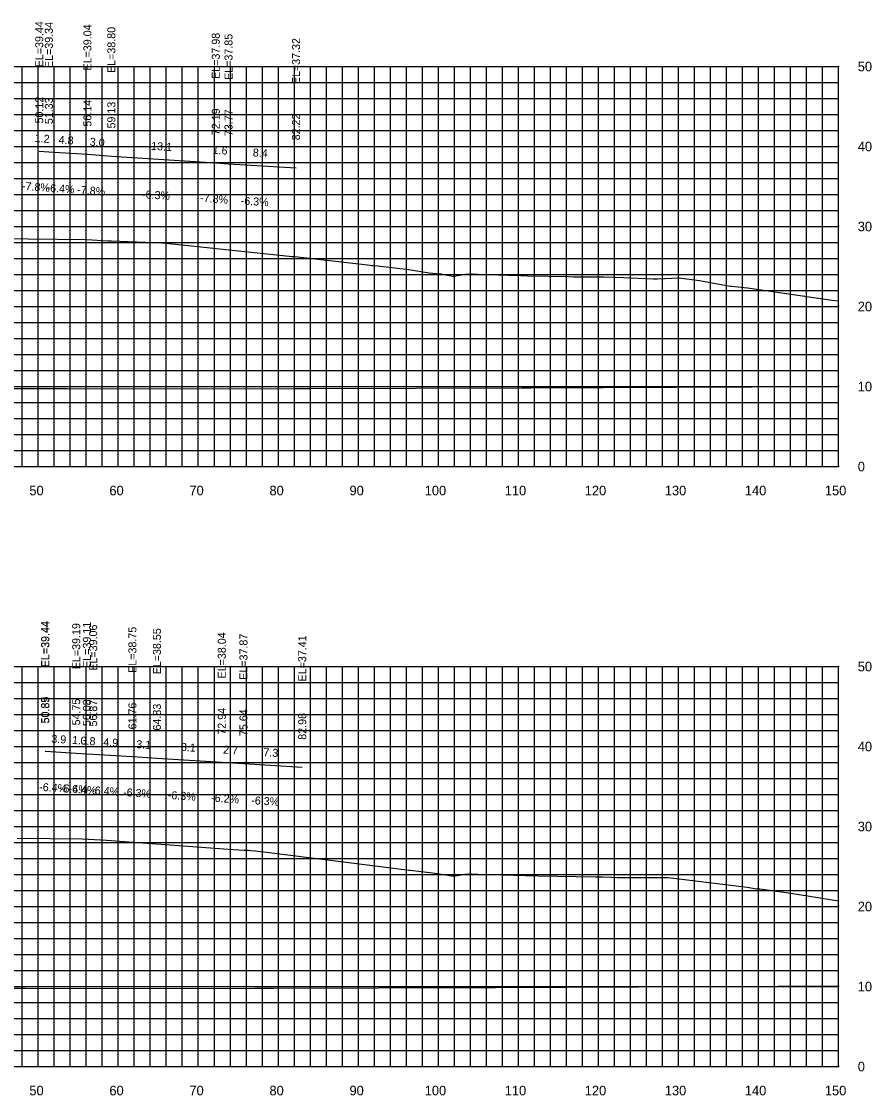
# Model space of a CAD drawing. Extents: x 1800880 to 1818864, y 245271 to 250560.
# Drawn here: x 1809796.4 to 1809902.6, y 249645.6 to 249779.8 of the extents above; entities that cross this region are included whole.
import ezdxf

# ---------------------------------------------------------------- set-up
doc = ezdxf.new("R2010")
doc.units = 0
for name, color, linetype in [('33', 7, 'Continuous'), ('ANNO-TXT', 7, 'Continuous'), ('CL-CNST', 7, 'Continuous'), ('DESIGN - DRAINAGE - Bridges', 7, 'Continuous'), ('Level 46', 7, 'Continuous'), ('Level 62', 7, 'Continuous'), ('SHT-BDR', 7, 'Continuous')]:
    doc.layers.add(name, color=color, linetype=linetype)

msp = doc.modelspace()

# ---------------------------------------------------------------- linework, layer by layer
at = {"layer": 'CL-CNST'}
for points in [[(1809793.4, 249752.72), (1809804.54, 249752.59), (1809807.17, 249752.44), (1809807.6, 249752.41), (1809811.85, 249752.25), (1809812.56, 249752.22), (1809812.83, 249752.21), (1809813.2, 249752.21), (1809813.38, 249752.2), (1809814.77, 249752.11), (1809814.81, 249752.11), (1809830.2, 249750.48), (1809830.5, 249750.49), (1809839.58, 249749.41), (1809839.91, 249749.37), (1809840.16, 249749.33), (1809840.51, 249749.33), (1809844.76, 249748.85), (1809847.31, 249748.45), (1809848.69, 249748.32), (1809848.81, 249748.29), (1809848.87, 249748.27), (1809848.88, 249748.27), (1809850.26, 249748.02), (1809850.3, 249748.02), (1809850.4, 249748.03), (1809851.79, 249748.28), (1809852.58, 249748.28), (1809852.62, 249748.29), (1809852.65, 249748.29), (1809852.69, 249748.29), (1809852.7, 249748.29), (1809853.4, 249748.26), (1809857.14, 249748.15), (1809858.73, 249748.1), (1809859.6, 249748.07), (1809864.73, 249747.96), (1809865.36, 249747.95), (1809865.6, 249747.95), (1809866.69, 249747.95), (1809869.08, 249747.92), (1809871.57, 249747.83), (1809875.29, 249747.69), (1809875.83, 249747.69), (1809878.54, 249747.8), (1809881.1, 249747.48), (1809884.9, 249746.76), (1809885.07, 249746.76), (1809887.07, 249746.55), (1809897.66, 249745.03), (1809898.46, 249744.91)], [(1809795.84, 249677.76), (1809803.93, 249677.67), (1809806.26, 249677.54), (1809806.98, 249677.5), (1809822.21, 249676.41), (1809824.16, 249676.28), (1809824.72, 249676.27), (1809825.01, 249676.24), (1809825.01, 249676.24), (1809825.6, 249676.17), (1809827.32, 249675.97), (1809842.23, 249674.12), (1809844.76, 249673.77), (1809844.91, 249673.76), (1809847.01, 249673.5), (1809847.05, 249673.5), (1809848.34, 249673.35), (1809848.35, 249673.34), (1809848.8, 249673.28), (1809848.95, 249673.23), (1809849.13, 249673.23), (1809850.08, 249673.06), (1809850.11, 249673.06), (1809850.59, 249673.07), (1809851.78, 249673.28), (1809852.33, 249673.29), (1809852.35, 249673.29), (1809852.37, 249673.29), (1809852.4, 249673.29), (1809852.43, 249673.29), (1809852.47, 249673.29), (1809852.51, 249673.29), (1809852.56, 249673.29), (1809852.6, 249673.29), (1809853.37, 249673.27), (1809860.9, 249673.04), (1809868.07, 249672.93), (1809868.98, 249672.92), (1809870.04, 249672.89), (1809870.81, 249672.87), (1809871.12, 249672.86), (1809871.29, 249672.86), (1809871.39, 249672.85), (1809871.47, 249672.85), (1809871.76, 249672.84), (1809871.99, 249672.87), (1809875.13, 249672.86), (1809875.84, 249672.87), (1809876.37, 249672.87), (1809876.89, 249672.87), (1809877.03, 249672.87), (1809877.1, 249672.87), (1809877.18, 249672.87), (1809887.05, 249671.64), (1809888.21, 249671.42), (1809888.63, 249671.42), (1809889.24, 249671.35), (1809892.48, 249670.89), (1809898.46, 249669.94)]]:
    msp.add_lwpolyline(points, dxfattribs=at)
at = {"layer": 'DESIGN - DRAINAGE - Bridges'}
for p, q in [((1809898.46, 249724.22), (1809898.46, 249774.22)), ((1809898.52, 249774.22), (1809898.46, 249774.22)), ((1809898.52, 249764.22), (1809898.46, 249764.22)), ((1809898.52, 249754.22), (1809898.46, 249754.22)), ((1809898.52, 249744.22), (1809898.46, 249744.22)), ((1809898.52, 249734.22), (1809898.46, 249734.22)), ((1809598.46, 249724.22), (1809898.46, 249724.22)), ((1809798.46, 249724.16), (1809798.46, 249724.22)), ((1809808.46, 249724.16), (1809808.46, 249724.22)), ((1809818.46, 249724.16), (1809818.46, 249724.22)), ((1809828.46, 249724.16), (1809828.46, 249724.22)), ((1809838.46, 249724.16), (1809838.46, 249724.22)), ((1809848.46, 249724.16), (1809848.46, 249724.22)), ((1809858.46, 249724.16), (1809858.46, 249724.22)), ((1809868.46, 249724.16), (1809868.46, 249724.22)), ((1809878.46, 249724.16), (1809878.46, 249724.22)), ((1809888.46, 249724.16), (1809888.46, 249724.22)), ((1809898.46, 249724.16), (1809898.46, 249724.22)), ((1809898.52, 249724.22), (1809898.46, 249724.22)), ((1809898.46, 249649.22), (1809898.46, 249699.22)), ((1809898.52, 249699.22), (1809898.46, 249699.22)), ((1809898.52, 249689.22), (1809898.46, 249689.22)), ((1809898.52, 249679.22), (1809898.46, 249679.22)), ((1809898.52, 249669.22), (1809898.46, 249669.22)), ((1809898.52, 249659.22), (1809898.46, 249659.22)), ((1809598.46, 249649.22), (1809898.46, 249649.22)), ((1809798.46, 249649.16), (1809798.46, 249649.22)), ((1809808.46, 249649.16), (1809808.46, 249649.22)), ((1809818.46, 249649.16), (1809818.46, 249649.22)), ((1809828.46, 249649.16), (1809828.46, 249649.22)), ((1809838.46, 249649.16), (1809838.46, 249649.22)), ((1809848.46, 249649.16), (1809848.46, 249649.22)), ((1809858.46, 249649.16), (1809858.46, 249649.22)), ((1809868.46, 249649.16), (1809868.46, 249649.22)), ((1809878.46, 249649.16), (1809878.46, 249649.22)), ((1809888.46, 249649.16), (1809888.46, 249649.22)), ((1809898.46, 249649.16), (1809898.46, 249649.22)), ((1809898.52, 249649.22), (1809898.46, 249649.22))]:
    msp.add_line(p, q, dxfattribs=at)
at = {"layer": 'Level 46'}
for p, q in [((1809598.46, 249774.22), (1809898.46, 249774.22)), ((1809796.46, 249724.22), (1809796.46, 249774.22)), ((1809798.46, 249724.22), (1809798.46, 249774.22)), ((1809800.46, 249724.22), (1809800.46, 249774.22)), ((1809802.46, 249724.22), (1809802.46, 249774.22)), ((1809804.46, 249724.22), (1809804.46, 249774.22)), ((1809806.46, 249724.22), (1809806.46, 249774.22)), ((1809808.46, 249724.22), (1809808.46, 249774.22)), ((1809810.46, 249724.22), (1809810.46, 249774.22)), ((1809812.46, 249724.22), (1809812.46, 249774.22)), ((1809814.46, 249724.22), (1809814.46, 249774.22)), ((1809816.46, 249724.22), (1809816.46, 249774.22)), ((1809818.46, 249724.22), (1809818.46, 249774.22)), ((1809820.46, 249724.22), (1809820.46, 249774.22)), ((1809822.46, 249724.22), (1809822.46, 249774.22)), ((1809824.46, 249724.22), (1809824.46, 249774.22)), ((1809826.46, 249724.22), (1809826.46, 249774.22)), ((1809828.46, 249724.22), (1809828.46, 249774.22)), ((1809830.46, 249724.22), (1809830.46, 249774.22)), ((1809832.46, 249724.22), (1809832.46, 249774.22)), ((1809834.46, 249724.22), (1809834.46, 249774.22)), ((1809836.46, 249724.22), (1809836.46, 249774.22)), ((1809838.46, 249724.22), (1809838.46, 249774.22)), ((1809840.46, 249724.22), (1809840.46, 249774.22)), ((1809842.46, 249724.22), (1809842.46, 249774.22)), ((1809844.46, 249724.22), (1809844.46, 249774.22)), ((1809846.46, 249724.22), (1809846.46, 249774.22)), ((1809848.46, 249724.22), (1809848.46, 249774.22)), ((1809850.46, 249724.22), (1809850.46, 249774.22)), ((1809852.46, 249724.22), (1809852.46, 249774.22)), ((1809854.46, 249724.22), (1809854.46, 249774.22)), ((1809856.46, 249724.22), (1809856.46, 249774.22)), ((1809858.46, 249724.22), (1809858.46, 249774.22)), ((1809860.46, 249724.22), (1809860.46, 249774.22)), ((1809862.46, 249724.22), (1809862.46, 249774.22)), ((1809864.46, 249724.22), (1809864.46, 249774.22)), ((1809866.46, 249724.22), (1809866.46, 249774.22)), ((1809868.46, 249724.22), (1809868.46, 249774.22)), ((1809870.46, 249724.22), (1809870.46, 249774.22)), ((1809872.46, 249724.22), (1809872.46, 249774.22)), ((1809874.46, 249724.22), (1809874.46, 249774.22)), ((1809876.46, 249724.22), (1809876.46, 249774.22)), ((1809878.46, 249724.22), (1809878.46, 249774.22)), ((1809880.46, 249724.22), (1809880.46, 249774.22)), ((1809882.46, 249724.22), (1809882.46, 249774.22)), ((1809884.46, 249724.22), (1809884.46, 249774.22)), ((1809886.46, 249724.22), (1809886.46, 249774.22)), ((1809888.46, 249724.22), (1809888.46, 249774.22)), ((1809890.46, 249724.22), (1809890.46, 249774.22)), ((1809892.46, 249724.22), (1809892.46, 249774.22)), ((1809894.46, 249724.22), (1809894.46, 249774.22)), ((1809896.46, 249724.22), (1809896.46, 249774.22)), ((1809898.46, 249724.22), (1809898.46, 249774.22)), ((1809598.46, 249772.22), (1809898.46, 249772.22)), ((1809598.46, 249770.22), (1809898.46, 249770.22)), ((1809598.46, 249768.22), (1809898.46, 249768.22)), ((1809598.46, 249766.22), (1809898.46, 249766.22)), ((1809598.46, 249764.22), (1809898.46, 249764.22)), ((1809598.46, 249762.22), (1809898.46, 249762.22)), ((1809598.46, 249760.22), (1809898.46, 249760.22)), ((1809598.46, 249758.22), (1809898.46, 249758.22)), ((1809598.46, 249756.22), (1809898.46, 249756.22)), ((1809598.46, 249754.22), (1809898.46, 249754.22)), ((1809598.46, 249752.22), (1809898.46, 249752.22)), ((1809598.46, 249750.22), (1809898.46, 249750.22)), ((1809598.46, 249748.22), (1809898.46, 249748.22)), ((1809598.46, 249746.22), (1809898.46, 249746.22)), ((1809598.46, 249744.22), (1809898.46, 249744.22)), ((1809598.46, 249742.22), (1809898.46, 249742.22)), ((1809598.46, 249740.22), (1809898.46, 249740.22)), ((1809598.46, 249738.22), (1809898.46, 249738.22)), ((1809598.46, 249736.22), (1809898.46, 249736.22)), ((1809598.46, 249734.22), (1809898.46, 249734.22)), ((1809598.46, 249732.22), (1809898.46, 249732.22)), ((1809598.46, 249730.22), (1809898.46, 249730.22)), ((1809598.46, 249728.22), (1809898.46, 249728.22)), ((1809598.46, 249726.22), (1809898.46, 249726.22)), ((1809598.46, 249724.22), (1809898.46, 249724.22)), ((1809598.46, 249699.22), (1809898.46, 249699.22)), ((1809796.46, 249649.22), (1809796.46, 249699.22)), ((1809798.46, 249649.22), (1809798.46, 249699.22)), ((1809800.46, 249649.22), (1809800.46, 249699.22)), ((1809802.46, 249649.22), (1809802.46, 249699.22)), ((1809804.46, 249649.22), (1809804.46, 249699.22)), ((1809806.46, 249649.22), (1809806.46, 249699.22)), ((1809808.46, 249649.22), (1809808.46, 249699.22)), ((1809810.46, 249649.22), (1809810.46, 249699.22)), ((1809812.46, 249649.22), (1809812.46, 249699.22)), ((1809814.46, 249649.22), (1809814.46, 249699.22)), ((1809816.46, 249649.22), (1809816.46, 249699.22)), ((1809818.46, 249649.22), (1809818.46, 249699.22)), ((1809820.46, 249649.22), (1809820.46, 249699.22)), ((1809822.46, 249649.22), (1809822.46, 249699.22)), ((1809824.46, 249649.22), (1809824.46, 249699.22)), ((1809826.46, 249649.22), (1809826.46, 249699.22)), ((1809828.46, 249649.22), (1809828.46, 249699.22)), ((1809830.46, 249649.22), (1809830.46, 249699.22)), ((1809832.46, 249649.22), (1809832.46, 249699.22)), ((1809834.46, 249649.22), (1809834.46, 249699.22)), ((1809836.46, 249649.22), (1809836.46, 249699.22)), ((1809838.46, 249649.22), (1809838.46, 249699.22)), ((1809840.46, 249649.22), (1809840.46, 249699.22)), ((1809842.46, 249649.22), (1809842.46, 249699.22)), ((1809844.46, 249649.22), (1809844.46, 249699.22)), ((1809846.46, 249649.22), (1809846.46, 249699.22)), ((1809848.46, 249649.22), (1809848.46, 249699.22)), ((1809850.46, 249649.22), (1809850.46, 249699.22)), ((1809852.46, 249649.22), (1809852.46, 249699.22)), ((1809854.46, 249649.22), (1809854.46, 249699.22)), ((1809856.46, 249649.22), (1809856.46, 249699.22)), ((1809858.46, 249649.22), (1809858.46, 249699.22)), ((1809860.46, 249649.22), (1809860.46, 249699.22)), ((1809862.46, 249649.22), (1809862.46, 249699.22)), ((1809864.46, 249649.22), (1809864.46, 249699.22)), ((1809866.46, 249649.22), (1809866.46, 249699.22)), ((1809868.46, 249649.22), (1809868.46, 249699.22)), ((1809870.46, 249649.22), (1809870.46, 249699.22)), ((1809872.46, 249649.22), (1809872.46, 249699.22)), ((1809874.46, 249649.22), (1809874.46, 249699.22)), ((1809876.46, 249649.22), (1809876.46, 249699.22)), ((1809878.46, 249649.22), (1809878.46, 249699.22)), ((1809880.46, 249649.22), (1809880.46, 249699.22)), ((1809882.46, 249649.22), (1809882.46, 249699.22)), ((1809884.46, 249649.22), (1809884.46, 249699.22)), ((1809886.46, 249649.22), (1809886.46, 249699.22)), ((1809888.46, 249649.22), (1809888.46, 249699.22)), ((1809890.46, 249649.22), (1809890.46, 249699.22)), ((1809892.46, 249649.22), (1809892.46, 249699.22)), ((1809894.46, 249649.22), (1809894.46, 249699.22)), ((1809896.46, 249649.22), (1809896.46, 249699.22)), ((1809898.46, 249649.22), (1809898.46, 249699.22)), ((1809598.46, 249697.22), (1809898.46, 249697.22)), ((1809598.46, 249695.22), (1809898.46, 249695.22)), ((1809598.46, 249693.22), (1809898.46, 249693.22)), ((1809598.46, 249691.22), (1809898.46, 249691.22)), ((1809598.46, 249689.22), (1809898.46, 249689.22)), ((1809598.46, 249687.22), (1809898.46, 249687.22)), ((1809598.46, 249685.22), (1809898.46, 249685.22)), ((1809598.46, 249683.22), (1809898.46, 249683.22)), ((1809598.46, 249681.22), (1809898.46, 249681.22)), ((1809598.46, 249679.22), (1809898.46, 249679.22)), ((1809598.46, 249677.22), (1809898.46, 249677.22)), ((1809598.46, 249675.22), (1809898.46, 249675.22)), ((1809598.46, 249673.22), (1809898.46, 249673.22)), ((1809598.46, 249671.22), (1809898.46, 249671.22)), ((1809598.46, 249669.22), (1809898.46, 249669.22)), ((1809598.46, 249667.22), (1809898.46, 249667.22)), ((1809598.46, 249665.22), (1809898.46, 249665.22)), ((1809598.46, 249663.22), (1809898.46, 249663.22)), ((1809598.46, 249661.22), (1809898.46, 249661.22)), ((1809598.46, 249659.22), (1809898.46, 249659.22)), ((1809598.46, 249657.22), (1809898.46, 249657.22)), ((1809598.46, 249655.22), (1809898.46, 249655.22)), ((1809598.46, 249653.22), (1809898.46, 249653.22)), ((1809598.46, 249651.22), (1809898.46, 249651.22)), ((1809598.46, 249649.22), (1809898.46, 249649.22))]:
    msp.add_line(p, q, dxfattribs=at)
at = {"layer": 'Level 62'}
for points in [[(1809798.58, 249763.65), (1809799.78, 249763.56), (1809804.6, 249763.25), (1809807.59, 249763.02), (1809820.64, 249762.19), (1809822.23, 249762.07), (1809830.67, 249761.54)], [(1809598.46, 249735.72), (1809611.25, 249735.23), (1809623.59, 249735.11), (1809638.89, 249734.77), (1809655.22, 249734.63), (1809666.53, 249734.49), (1809685.64, 249734.37), (1809694.17, 249734.29), (1809715.32, 249734.19), (1809721.81, 249734.14), (1809744.54, 249734.06), (1809749.45, 249734.02), (1809773.42, 249733.98), (1809777.09, 249733.96), (1809802.07, 249733.96), (1809804.73, 249733.94), (1809830.55, 249733.98), (1809832.37, 249733.97), (1809858.89, 249734.05), (1809860.01, 249734.05), (1809887.13, 249734.18), (1809887.65, 249734.18), (1809898.46, 249734.24)], [(1809799.31, 249688.66), (1809799.35, 249688.65), (1809803.2, 249688.41), (1809804.53, 249688.32), (1809805.32, 249688.27), (1809810.22, 249687.96), (1809813.29, 249687.77), (1809821.39, 249687.25), (1809824.1, 249687.09), (1809831.44, 249686.62)], [(1809598.46, 249660.63), (1809606.04, 249660.34), (1809616.86, 249660.23), (1809633.77, 249659.85), (1809648.89, 249659.73), (1809661.5, 249659.57), (1809679.62, 249659.45), (1809689.23, 249659.36), (1809709.56, 249659.26), (1809716.96, 249659.21), (1809738.99, 249659.13), (1809744.69, 249659.08), (1809768.06, 249659.04), (1809772.42, 249659.02), (1809796.88, 249659.01), (1809800.15, 249658.99), (1809825.51, 249659.03), (1809827.88, 249659.01), (1809854, 249659.1), (1809855.61, 249659.09), (1809882.37, 249659.22), (1809883.34, 249659.22), (1809898.46, 249659.3)]]:
    msp.add_lwpolyline(points, dxfattribs=at)

# ---------------------------------------------------------------- texts
for s, p in [('50', (1809797.35, 249720.62)), ('60', (1809807.35, 249720.62)), ('70', (1809817.35, 249720.62)), ('80', (1809827.35, 249720.62)), ('90', (1809837.35, 249720.62)), ('100', (1809846.75, 249720.62)), ('110', (1809856.75, 249720.62)), ('120', (1809866.75, 249720.62)), ('130', (1809876.75, 249720.62)), ('140', (1809886.75, 249720.62)), ('150', (1809896.75, 249720.62)), ('50', (1809797.35, 249645.62)), ('60', (1809807.35, 249645.62)), ('70', (1809817.35, 249645.62)), ('80', (1809827.35, 249645.62)), ('90', (1809837.35, 249645.62)), ('100', (1809846.75, 249645.62)), ('110', (1809856.75, 249645.62)), ('120', (1809866.75, 249645.62)), ('130', (1809876.75, 249645.62)), ('140', (1809886.75, 249645.62)), ('150', (1809896.75, 249645.62))]:
    msp.add_text(s, height=1.2).set_placement(p)
at = {"layer": '33'}
for s, p in [('50', (1809900.86, 249773.62)), ('40', (1809900.86, 249763.62)), ('30', (1809900.86, 249753.62)), ('20', (1809900.86, 249743.62)), ('10', (1809900.86, 249733.62)), ('0', (1809900.86, 249723.62)), ('50', (1809900.86, 249698.62)), ('40', (1809900.86, 249688.62)), ('30', (1809900.86, 249678.62)), ('20', (1809900.86, 249668.62)), ('10', (1809900.86, 249658.62)), ('0', (1809900.86, 249648.62))]:
    msp.add_text(s, height=1.2, dxfattribs=at).set_placement(p)
at = {"layer": 'ANNO-TXT'}
for s, rotation, p in [('1.2', 355.5357, (1809797.99, 249764.8)), ('4.8', 356.3601, (1809800.98, 249764.58)), ('3.0', 355.5413, (1809804.86, 249764.33)), ('13.1', 356.3869, (1809812.54, 249763.81)), ('1.6', 355.5566, (1809820.22, 249763.33)), ('8.4', 356.404, (1809825.24, 249762.98)), ('-7.8%', 355.5357, (1809796.39, 249758.81)), ('-6.4%', 356.3601, (1809799.47, 249758.57)), ('-7.8%', 355.5413, (1809803.3, 249758.34)), ('-6.3%', 356.3869, (1809811.4, 249757.77)), ('-7.8%', 355.5566, (1809818.65, 249757.33)), ('-6.3%', 356.404, (1809823.73, 249756.97)), ('3.9', 356.3573, (1809800.07, 249689.71)), ('1.3', 356.3353, (1809802.66, 249689.55)), ('0.8', 356.3601, (1809803.72, 249689.48)), ('4.9', 356.3446, (1809806.56, 249689.3)), ('3.1', 356.3849, (1809810.67, 249689.03)), ('8.1', 356.383, (1809816.26, 249688.68)), ('2.7', 356.4449, (1809821.53, 249688.35)), ('7.3', 356.3985, (1809826.56, 249688.03)), ('-6.4%', 356.3573, (1809798.55, 249683.69)), ('-6.4%', 356.3353, (1809801.14, 249683.53)), ('-6.4%', 356.3601, (1809802.21, 249683.46)), ('-6.4%', 356.3446, (1809805.05, 249683.28)), ('-6.3%', 356.3849, (1809809.03, 249683.03)), ('-6.3%', 356.383, (1809814.62, 249682.67)), ('-6.2%', 356.4449, (1809820.03, 249682.33)), ('-6.3%', 356.3985, (1809825.05, 249682.02))]:
    msp.add_text(s, height=1, rotation=rotation, dxfattribs=at).set_placement(p)
at = {"layer": 'SHT-BDR'}
for s, p in [('EL=39.44', (1809799.08, 249774.12)), ('EL=39.34', (1809800.28, 249774.03)), ('EL=39.04', (1809805.1, 249773.72)), ('EL=38.80', (1809808.09, 249773.41)), ('EL=37.98', (1809821.14, 249772.67)), ('EL=37.85', (1809822.73, 249772.54)), ('EL=37.32', (1809831.17, 249772.01)), ('50.12', (1809799.08, 249767.1)), ('51.33', (1809800.28, 249767.01)), ('56.14', (1809805.1, 249766.7)), ('59.13', (1809808.09, 249766.47)), ('72.19', (1809821.14, 249765.64)), ('73.77', (1809822.73, 249765.52)), ('82.22', (1809831.17, 249764.99)), ('EL=39.44', (1809799.81, 249699.13)), ('EL=39.44', (1809799.85, 249699.13)), ('EL=39.19', (1809803.7, 249698.88)), ('EL=39.11', (1809805.03, 249699.05)), ('EL=39.06', (1809805.82, 249698.7)), ('EL=38.75', (1809810.72, 249698.43)), ('EL=38.55', (1809813.79, 249698.24)), ('EL=38.04', (1809821.89, 249697.73)), ('EL=37.87', (1809824.6, 249697.56)), ('EL=37.41', (1809831.94, 249697.35)), ('50.85', (1809799.81, 249692.11)), ('50.89', (1809799.85, 249692.1)), ('54.75', (1809803.7, 249691.86)), ('56.08', (1809805.03, 249691.77)), ('56.87', (1809805.82, 249691.72)), ('61.76', (1809810.72, 249691.36)), ('64.83', (1809813.79, 249691.22)), ('72.94', (1809821.89, 249690.7)), ('75.64', (1809824.6, 249690.53)), ('82.98', (1809831.94, 249690.07))]:
    msp.add_text(s, height=1, rotation=90, dxfattribs=at).set_placement(p)

doc.saveas('drawing.dxf')
